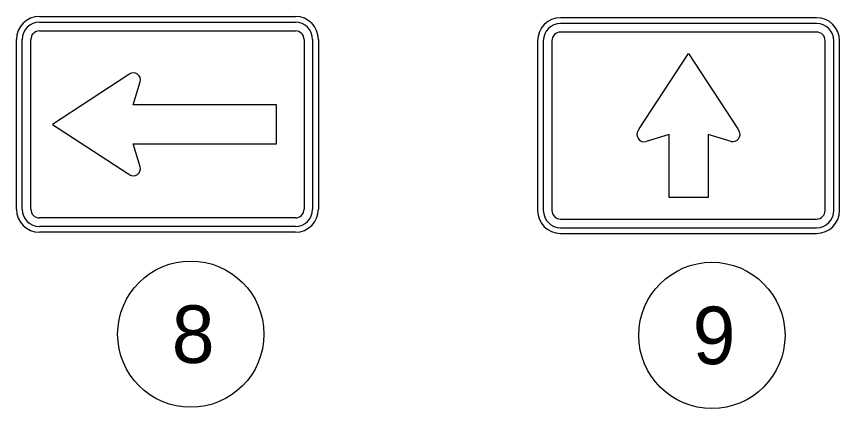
# Model space of a CAD drawing. Extents: x -2251611 to -2054719, y -2227156 to -2099355.
# Drawn here: x -2114636 to -2110342, y -2128451 to -2126406 of the extents above; entities that cross this region are included whole.
import ezdxf

# ---------------------------------------------------------------- set-up
doc = ezdxf.new("R2010")
doc.units = 0
doc.layers.add('Default', color=7, linetype='Continuous')
doc.layers.add('dsnTextNote', color=7, linetype='Continuous')

msp = doc.modelspace()

# ---------------------------------------------------------------- linework, layer by layer
at = {"layer": 'Default'}
for p, q in [((-2114515.6, -2126406.5), (-2113180.6, -2126406.5)), ((-2110462.4, -2126412.8), (-2111797.4, -2126412.8)), ((-2114515.6, -2126436.5), (-2113180.6, -2126436.5)), ((-2110462.4, -2126442.8), (-2111797.4, -2126442.8)), ((-2114515.6, -2126481.5), (-2113180.6, -2126481.5)), ((-2110462.4, -2126487.8), (-2111797.4, -2126487.8)), ((-2114635.6, -2127411.5), (-2114635.6, -2126526.5)), ((-2114605.6, -2127411.5), (-2114605.6, -2126526.5)), ((-2114560.6, -2127411.5), (-2114560.6, -2126526.5)), ((-2113135.6, -2126526.5), (-2113135.6, -2127411.5)), ((-2113090.6, -2126526.5), (-2113090.6, -2127411.5)), ((-2113060.6, -2126526.5), (-2113060.6, -2127411.5)), ((-2111917.4, -2126532.8), (-2111917.4, -2127417.8)), ((-2111887.4, -2126532.8), (-2111887.4, -2127417.8)), ((-2111842.4, -2126532.8), (-2111842.4, -2127417.8)), ((-2110417.4, -2127417.8), (-2110417.4, -2126532.8)), ((-2110372.4, -2127417.8), (-2110372.4, -2126532.8)), ((-2110342.4, -2127417.8), (-2110342.4, -2126532.8)), ((-2113180.6, -2127456.5), (-2114515.6, -2127456.5)), ((-2113180.6, -2127501.5), (-2114515.6, -2127501.5)), ((-2111797.4, -2127462.8), (-2110462.4, -2127462.8)), ((-2113180.6, -2127531.5), (-2114515.6, -2127531.5)), ((-2111797.4, -2127507.8), (-2110462.4, -2127507.8)), ((-2111797.4, -2127537.8), (-2110462.4, -2127537.8))]:
    msp.add_line(p, q, dxfattribs=at)
for points in [[(-2111387, -2126992.9), (-2111129.9, -2126600.3), (-2110873.5, -2126993)], [(-2114055.5, -2126711.8), (-2114448.1, -2126969), (-2114055.4, -2127225.3)], [(-2113990.7, -2127190.5), (-2114026.6, -2127070.5), (-2113279.3, -2127070.5), (-2113279.3, -2126867.4), (-2114026.6, -2126867.4), (-2113990.1, -2126747.6)], [(-2111028.3, -2127350.3), (-2111231.4, -2127350.3), (-2111231.4, -2127021.8), (-2111351.2, -2127058.4)], [(-2110908.3, -2127057.7), (-2111028.3, -2127021.8), (-2111028.3, -2127350.3)]]:
    msp.add_lwpolyline(points, dxfattribs=at)
for centre, radius, start, end in [((-2114515.6, -2126526.5), 120, 90, 180), ((-2113180.6, -2126526.5), 120, 0, 90), ((-2111797.4, -2126532.8), 120, 90, 180), ((-2110462.4, -2126532.8), 120, 0, 90), ((-2114515.6, -2126526.5), 90, 90, 180), ((-2113180.6, -2126526.5), 90, 0, 90), ((-2111797.4, -2126532.8), 90, 90, 180), ((-2110462.4, -2126532.8), 90, 0, 90), ((-2114515.6, -2126526.5), 45, 90, 180), ((-2113180.6, -2126526.5), 45, 0, 90), ((-2111797.4, -2126532.8), 45, 90, 180), ((-2110462.4, -2126532.8), 45, 0, 90), ((-2116110.4, -2123574.9), 3750, 303.2286, 303.3891), ((-2114026.1, -2126737.3), 37.5, 344.0309, 123.3891), ((-2111361.5, -2127022.3), 37.5, 146.6109, 285.9691), ((-2114523.9, -2124938), 3750, 326.6109, 326.7714), ((-2110898.2, -2127022.3), 36.8, 254.0309, 33.3104), ((-2107733.6, -2124942.7), 3750, 213.143, 213.3104), ((-2114026.1, -2127200.6), 36.8, 236.6896, 15.9691), ((-2116105.7, -2130365.2), 3750, 56.6896, 56.857), ((-2114515.6, -2127411.5), 120, 180, 270), ((-2114515.6, -2127411.5), 90, 180, 270), ((-2114515.6, -2127411.5), 45, 180, 270), ((-2113180.6, -2127411.5), 120, 270, 0), ((-2113180.6, -2127411.5), 90, 270, 0), ((-2113180.6, -2127411.5), 45, 270, 0), ((-2111797.4, -2127417.8), 120, 180, 270), ((-2111797.4, -2127417.8), 90, 180, 270), ((-2111797.4, -2127417.8), 45, 180, 270), ((-2110462.4, -2127417.8), 120, 270, 0), ((-2110462.4, -2127417.8), 90, 270, 360), ((-2110462.4, -2127417.8), 45, 270, 0)]:
    msp.add_arc(centre, radius, start, end, dxfattribs=at)
at = {"layer": 'dsnTextNote'}
for centre in [(-2113726.4, -2128062.9), (-2111008.2, -2128069.3)]:
    msp.add_circle(centre, 381.4, dxfattribs=at)

# ---------------------------------------------------------------- texts
for s, p in [('8', (-2113825.5, -2128212.9)), ('9', (-2111108.5, -2128219.3))]:
    msp.add_text(s, height=300, dxfattribs=at).set_placement(p)

doc.saveas('drawing.dxf')
